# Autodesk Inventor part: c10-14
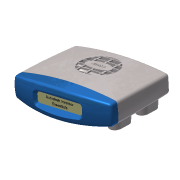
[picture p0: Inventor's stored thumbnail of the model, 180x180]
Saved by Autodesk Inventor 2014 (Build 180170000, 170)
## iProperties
Created: 2010-12
Part Number: c10-14
Material: Generic
Document SubType Name: Modeling
Designer: Thom Tremblay
Density: 1 g/cm^3
Appearance: Generic
Author: Thom Tremblay
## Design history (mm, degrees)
sketch "Sketch1"
  geometry: L1 (-60, -12)-(60, -12); L2 (60, -12)-(60, 12); L3 (60, 12)-(-60, 12); L4 (-60, 12)-(-60, -12); A1 r 350 centre (0, -332.819) between (60, 12) and (-60, 12); A2 r 350 centre (0, 332.819) between (-60, -12) and (60, -12); 3 further points
  constraints: 8 end point, 4 point on circle, 2 centre point, 2 midpoint, 2 parallel, 1 equal radius, 1 horizontal, 1 horizontal alignment, 1 perpendicular, 1 vertical alignment
  dimensions: "d0" = 120 distance of L3.end L2.end; "d1" = 24 distance of L2.end L1.end; "d2" = 350 radius of A1
workplane "Work Plane4"
sketch "Sketch5"
  geometry: L1 (-60, 12)-(-60, -12) reference; L2 (60, -12)-(60, 12) reference; L3 (-58, 10.314)-(-58, -10.314); L4 (58, -10.314)-(58, 10.314); A1 r 350 centre (0, 332.819) between (-60, -12) and (60, -12) reference; A2 r 350 centre (0, -332.819) between (60, 12) and (-60, 12) reference; A3 r 348 centre (0, 332.819) between (-58, -10.314) and (58, -10.314); A4 r 348 centre (0, -332.819) between (58, 10.314) and (-58, 10.314); 1 further point
  constraints: 4 end point, 4 point on circle, 2 centre point, 3 other
  dimensions: "d37" = 2 distance between parallel lines of L2 L4
sketch "Sketch6"
  geometry: L1 (-60, 0)-(60, 0); L2 (60, 0)-(58.843, 22.085); L3 (-60, 0)-(-58.779, 23.307); A1 r 691.758 centre (630.81, -36.204) between (-60, 0) and (-58, -100); A2 r 691.758 centre (-630.81, -36.204) between (58, -100) and (60, 0); 1 further point
  constraints: 6 end point, 4 point on circle, 2 centre point, 2 tangent, 1 horizontal
  dimensions: "d53" = 87 deg angle of L1 L3; "d54" = 87 deg angle of L1 L2 (= d53)
sketch "Sketch7"
  geometry: L1 (17.181, 0)-(12, 0) reference; L2 (15.181, -100)-(10.314, -100) reference; L3 (17.181, 0)-(16.768, 11.838); A1 r 911.322 centre (-893.585, -31.805) between (15.181, -100) and (17.181, 0); 1 further point
  constraints: 2 end point, 2 point on circle, 1 centre point, 1 tangent
  dimensions: "d56" = 88 deg angle of L1 L3
feature "LoftSrf2" sketch "Sketch5", "Sketch6", "Sketch7" dims "d57" = 0, "d58" = 90 deg, "d59" = 0, "d60" = 90 deg, "d61" = 0, "d62" = 90 deg, "d63" = 0, "d64" = 90 deg, "d65" = 0, "d66" = 90 deg
sketch "Sketch2"
  geometry: L1 (-75, -16)-(75, -16); L2 (-75, -60)-(75, -60); A1 r 183.781 centre (0, -183.781) between (75, -16) and (-75, -16); 2 further points
  constraints: 4 end point, 3 point on circle, 1 centre point, 1 coincident, 1 horizontal, 1 parallel
  dimensions: "d5" = 16 distance from line of point (0, 0) L1; "d7" = 60 distance from line of point (0, 0) L2; "d55" = 150 distance of L1.start L1.end
feature "RevolutionSrf1" sketch "Sketch2" dims angle "d8" = 40 deg
patch "Boundary Patch1" dims "d13" = 0, "d67" = 0, "d68" = 0, "d69" = 0, "d70" = 0
workplane "Work Plane1"
sketch "Sketch3"
  geometry: L1 (52, -85)-(52, -73); L2 (38, -73)-(38, -85); A1 r 7 centre (45, -73) between (52, -73) and (38, -73); A2 r 7 centre (45, -85) between (38, -85) and (52, -85); 1 further point
  constraints: 4 end point, 4 point on circle, 4 tangent, 2 centre point, 1 parallel, 1 vertical
  dimensions: "d15" = 12 distance of L1.start L1.end; "d16" = 7 radius of A1; "d50" = 45 horizontal distance of A1.centre point (0, 0); "d51" = 85 vertical distance of point (0, 0) A2.centre
extrude_surface "ExtrusionSrf2" sketch "Sketch3" dims "d19" = 14, "d20" = 5 deg
pattern_linear "Rectangular Pattern1" dims "d23" = 90
workplane "Work Plane2"
feature "Sculpt1"
sketch "Sketch4"
  geometry: L1 (-24.5, 6)-(24.5, 6); L2 (27.5, 3)-(27.5, -3); L3 (24.5, -6)-(-24.5, -6); L4 (-27.5, -3)-(-27.5, 3); A1 r 3 centre (-24.5, 3) between (-24.5, 6) and (-27.5, 3); A2 r 3 centre (24.5, 3) between (27.5, 3) and (24.5, 6); A3 r 3 centre (24.5, -3) between (24.5, -6) and (27.5, -3); A4 r 3 centre (-24.5, -3) between (-27.5, -3) and (-24.5, -6); 6 further points
  constraints: 8 end point, 8 point on circle, 8 tangent, 6 point on line, 4 centre point, 3 equal radius, 2 midpoint, 2 parallel, 1 horizontal, 1 horizontal alignment, 1 perpendicular, 1 vertical alignment
  dimensions: "d28" = 55 distance of point (27.5, -6) point (-27.5, -6); "d29" = 12 distance of point (27.5, 6) point (27.5, -6); "d30" = 3 radius of A1
extrude_surface "ExtrusionSrf6" sketch "Sketch4" dims "d31" = 14, "d32" = 45 deg
patch "Boundary Patch2" dims "d33" = 0, "d34" = 0
fillet "Fillet1" dims "d79" = 4, "d80" = 3, "d81" = 1
feature "Sculpt2"
node "Splitting Plane 1"
shell "Shell1" dims "d83" = 2
split "Split1"
  body "Solid1"
feature "Lip1" dims "d188" = 1, "d189" = 1, "d190" = 0, "d191" = 0, "d192" = 0, "d193" = 0
feature "Lip2" dims "d194" = 1, "d195" = 1, "d196" = 0, "d197" = 0, "d198" = 0, "d199" = 0.5
split "Split3"
  node "Back"
sketch "Sketch9"
  geometry: L1 (50.167, -73)-(50.167, -85) reference; L2 (39.833, -85)-(39.833, -73) reference; L3 (45, -73)-(45, -85); L4 (45, -85)-(39.833, -85); A1 r 5.167 centre (45, -73) between (50.167, -73) and (39.833, -73) reference; A2 r 5.167 centre (45, -85) between (39.833, -85) and (50.167, -85) reference; 5 further points
  constraints: 4 end point, 1 horizontal, 1 midpoint, 1 parallel, 1 perpendicular, 1 vertical, 3 other
  dimensions: "d86" = 90 distance of point (45, -79) point (-45, -79); "d89" = 40 distance of point (45, -79) point (45, -39)
  node "Projected Loop1"
feature "Boss1" dims "d92" = 0, "d93" = 0, "d94" = 7, "d95" = 2, "d96" = 0.5, "d97" = 6, "d98" = 1.25, "d99" = 3.5, "d100" = 2.5 deg, "d101" = 2.5 deg, "d102" = 2.5 deg, "d103" = 2.5 deg, "d104" = 90 deg, "d107" = 2, "d108" = 2, "d109" = 10, "d110" = 0, "d111" = 10 deg, "d112" = 2.5 deg, "d113" = 0, "d114" = 0, "d115" = 0, "d116" = 360 deg
feature "Boss2" dims "d117" = 3, "d118" = 0, "d119" = 6, "d120" = 3, "d121" = 9.5, "d122" = 2 deg, "d123" = 1 deg, "d126" = 2, "d127" = 2, "d128" = 10, "d129" = 0, "d130" = 10 deg, "d131" = 2.5 deg, "d132" = 0, "d133" = 0, "d134" = 0, "d135" = 360 deg
workplane "Work Plane6"
sketch "Sketch10"
  geometry: L1 (24, -85)-(-24, -85); L2 (-30, -79)-(-30, -51); L3 (-24, -45)-(24, -45); L4 (30, -51)-(30, -79); L5 (54.344, -100)-(-54.344, -100) reference; A1 r 6 centre (-24, -51) between (-24, -45) and (-30, -51); A2 r 6 centre (24, -51) between (30, -51) and (24, -45); A3 r 6 centre (24, -79) between (24, -85) and (30, -79); A4 r 6 centre (-24, -79) between (-30, -79) and (-24, -85); 5 further points
  constraints: 8 end point, 8 point on circle, 8 tangent, 6 point on line, 4 centre point, 3 equal radius, 2 parallel, 1 horizontal, 1 midpoint, 1 perpendicular, 1 vertical alignment
  dimensions: "d137" = 60 distance of point (-30, -45) point (30, -45); "d138" = 40 distance of point (-30, -85) point (-30, -45); "d139" = 15 distance between parallel lines of L5 L1; "d141" = 6 radius of A2
feature "Rest1" sketch "Sketch10" dims "d142" = 5, "d143" = 0, "d144" = 0, "d145" = 0, "d146" = 2 deg, "d147" = 2 deg, "d148" = 2
feature "Rule Fillet1" dims "d149" = 2, "d150" = 1
workplane "Work Plane7"
sketch "Sketch11" dims "d154" = 16, "d155" = 8, "d161" = 10, "d168" = 10
  geometry: L1 (-13, -39.858)-(-13, -90.142); L2 (-25.187, -85)-(29.449, -85); L3 (0, -39.858)-(0, -90.142); L4 (13, -39.858)-(13, -90.142); L5 (-25.187, -77)-(29.449, -77); L6 (-25.187, -69)-(29.449, -69); L7 (-25.187, -61)-(29.449, -61); L8 (-25.187, -53)-(29.449, -53); L9 (-25.187, -45)-(29.449, -45); C1 r 22.5 at (0, -65); 3 further points; 1 other entity
  constraints: 18 end point, 2 coincident, 2 vertical, 1 centre point, 1 horizontal, 1 midpoint, 1 perpendicular, 1 vertical alignment, 23 other
  dimensions: "d152" = 45 diameter of C1; "d153" = 65 distance of point (0, 0) C1.centre; "d158" = 13 distance of L1.start L3.start; "d165" = 8 distance of L2.start L5.start; "d170" = 4 distance from line of L7 point (0, -65)
feature "Grill1" sketch "Sketch11" dims "d173" = 2, "d174" = 0, "d175" = 1, "d176" = 2, "d177" = 0, "d178" = 1, "d179" = 0.5, "d180" = 0, "d181" = 2, "d182" = 1, "d183" = 2 deg, "d184" = 0, "d185" = 88.84492
sketch "Sketch12"
  geometry: L1 (-12.481, -61.203)-(12.401, -61.203); L2 (12.401, -61.203)-(12.401, -68.714); L3 (12.401, -68.714)-(-12.481, -68.714); L4 (-12.481, -68.714)-(-12.481, -61.203); 1 further point
  constraints: 2 other
emboss "Emboss1" sketch "Sketch12" dims "d20" = 5 deg, "d186" = 0.5, "d187" = 0
sketch "Sketch13"
  geometry: L1 (0, 15.66)-(0, -14.781); 6 further points
  constraints: 2 end point, 1 coincident, 1 point on line, 1 vertical, 4 other
feature "Snap Fit1" sketch "Sketch13" dims "d200" = 4, "d201" = 2.5, "d202" = 1, "d203" = 0.9, "d204" = 10.2, "d205" = 10, "d206" = 1, "d207" = 1, "d208" = 50 deg, "d209" = 50 deg
fillet "Fillet2" dims "d213" = 2
workplane "Work Plane8"
sketch "Sketch14"
  geometry: L1 (-8.644, -6.828)-(57.644, -6.828); L2 (6.5, 3.689)-(6.5, -17.346); L3 (24.5, 3.689)-(24.5, -17.346); L4 (42.5, 3.689)-(42.5, -17.346); 2 further points
  constraints: 8 end point, 4 parallel, 2 horizontal alignment, 2 midpoint, 1 coincident, 1 horizontal, 1 perpendicular
  dimensions: "d211" = 18 distance between parallel lines of L3 L2; "d212" = 18 distance between parallel lines of L4 L3 (= d211)
feature "Rib1" sketch "Sketch14" dims "d214" = 2, "d215" = 1, "d216" = 5 deg, "d217" = 0, "d218" = 1, "d219" = 1
sketch "Sketch15"
  geometry: L1 (-30, 10)-(30, 10); L2 (30, 10)-(30, -10); L3 (30, -10)-(-30, -9.999); L4 (-30, -9.999)-(-30, 10); 3 further points; 1 other entity
  constraints: 2 midpoint, 1 horizontal alignment, 1 vertical alignment, 2 other
  dimensions: "d221" = 60 distance of L1.start L1.end
feature "Decal1" sketch "Sketch15"
body "Srf2"
body "Srf3"
body "Srf4"
body "Srf5"
body "Srf6"
body "Srf7"
body "Srf8"
body "Srf9"
body "Srf11"
feature "Stitch Surface1"
body "Srf12"
node "Image1"
extrude_surface "ExtrusionSrf3"
extrude_surface "ExtrusionSrf4"
extrude_surface "ExtrusionSrf5"
node "Front"
node "Back - Top"
node "Back - Bottom"
other parameters: "d14" = -24, "d52" = -6, "d171" = 1, "d172" = 2, "d210" = -1
